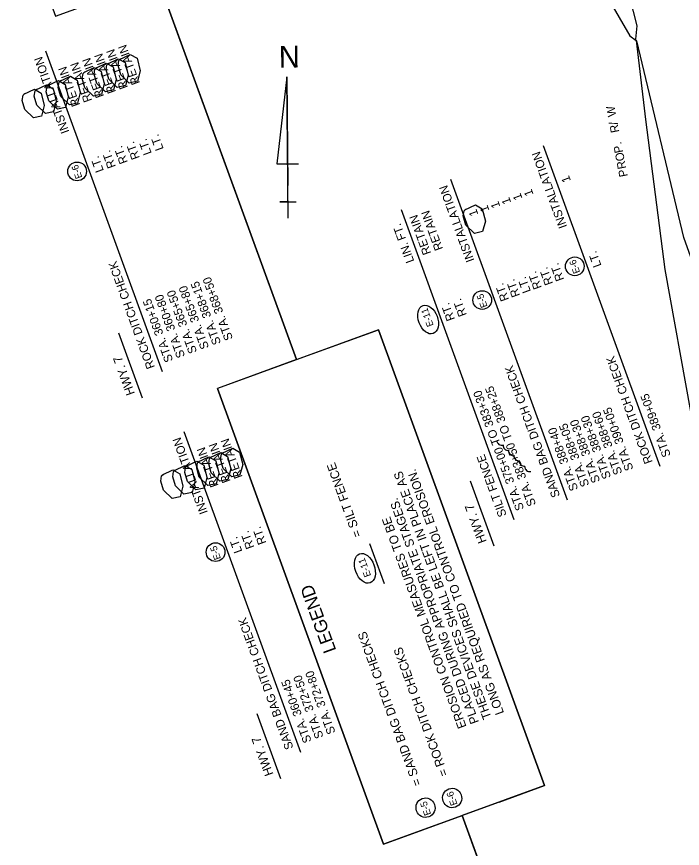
# Model space of a CAD drawing. Extents: x 960650 to 962115, y 1906901 to 1908757.
# Drawn here: x 961228 to 961698, y 1907282 to 1907870 of the extents above; entities that cross this region are included whole.
import ezdxf

# ---------------------------------------------------------------- set-up
doc = ezdxf.new("R2010")
doc.units = 0
for name, color, linetype in [('1', 7, 'Continuous'), ('44', 7, 'Continuous'), ('63', 7, 'Continuous'), ('Level 1', 7, 'Continuous'), ('Level 44', 7, 'Continuous'), ('NO PLOT', 7, 'Continuous'), ('R_Draft', 7, 'Continuous'), ('S_TREE', 7, 'Continuous')]:
    doc.layers.add(name, color=color, linetype=linetype)

msp = doc.modelspace()

# ---------------------------------------------------------------- linework, layer by layer
at = {"layer": '1'}
for p, q in [((961425.36, 1907627.47), (961327.48, 1907896.39)), ((961483.4, 1907648.6), (961369.64, 1907607.19)), ((961486.84, 1907285.2), (961369.64, 1907607.19)), ((961568.72, 1907315), (961486.84, 1907285.2)), ((961624.82, 1907079.46), (961542.56, 1907305.48))]:
    msp.add_line(p, q, dxfattribs=at)
msp.add_lwpolyline([(961568.72, 1907315), (961600.59, 1907326.6), (961483.4, 1907648.6)], dxfattribs=at)
for centre in [(961270.45, 1907760.38), (961622.07, 1907693.36), (961556.67, 1907669.56), (961368.3, 1907491.54)]:
    msp.add_circle(centre, 6.61, dxfattribs=at)
msp.add_ellipse((961518.44, 1907655.78), major_axis=(-3.6, 9.89), ratio=0.638788, dxfattribs=at)
at = {"layer": '44'}
for p, q in [((961330.68, 1907618.95), (961248.25, 1907845.42)), ((961682.37, 1907551.96), (961599.94, 1907778.43)), ((961616.91, 1907528.13), (961534.48, 1907754.6)), ((961579.17, 1907514.4), (961499.55, 1907733.16)), ((961316.61, 1907600.33), (961299.91, 1907646.22)), ((961428.53, 1907350.11), (961346.1, 1907576.58)), ((961565.1, 1907495.78), (961548.39, 1907541.67)), ((961414.46, 1907331.49), (961397.76, 1907377.38))]:
    msp.add_line(p, q, dxfattribs=at)
at = {"layer": '63'}
for p, q in [((961418.69, 1907827.3), (961411.58, 1907765.69)), ((961419.63, 1907727.31), (961418.69, 1907827.3)), ((961418.69, 1907827.3), (961419.41, 1907750.38)), ((961411.58, 1907765.69), (961426.96, 1907765.84)), ((961419.63, 1907727.31), (961419.41, 1907750.38)), ((961413.75, 1907738.79), (961425.29, 1907738.9)), ((961419.52, 1907738.84), (961413.75, 1907738.79)), ((961419.63, 1907727.31), (961419.52, 1907738.84))]:
    msp.add_line(p, q, dxfattribs=at)
at = {"layer": 'Level 1'}
for centre, major_axis, ratio in [((961473.76, 1907480.1), (-3.75, 10.3), 0.622952), ((961535.42, 1907317.88), (2.35, -6.47), 0.97521), ((961516.62, 1907311.04), (2.35, -6.47), 0.97521)]:
    msp.add_ellipse(centre, major_axis=major_axis, ratio=ratio, dxfattribs=at)
at = {"layer": 'Level 44'}
msp.add_lwpolyline([(961487.68, 1907469.14), (961477.37, 1907497.45)], dxfattribs=at)
at = {"layer": 'NO PLOT'}
for points in [[(962114.55, 1907257.7), (961568.91, 1908756.85), (961079.18, 1908578.6), (961182.12, 1908295.76), (961245.55, 1908318.85), (961390.91, 1907919.48), (961327.48, 1907896.39), (961425.36, 1907627.47), (961483.4, 1907648.6), (961600.59, 1907326.6), (961542.56, 1907305.48), (961624.82, 1907079.46)], [(962114.55, 1907257.7), (961568.91, 1908756.85), (961079.18, 1908578.6), (961182.12, 1908295.76), (961245.55, 1908318.85), (961390.91, 1907919.48), (961327.48, 1907896.39), (961425.36, 1907627.47), (961483.4, 1907648.6), (961600.59, 1907326.6), (961542.56, 1907305.48), (961624.82, 1907079.46)], [(962114.55, 1907257.7), (961568.91, 1908756.85), (961079.18, 1908578.6), (961182.12, 1908295.76), (961245.55, 1908318.85), (961390.91, 1907919.48), (961327.48, 1907896.39), (961425.36, 1907627.47), (961483.4, 1907648.6), (961600.59, 1907326.6), (961542.56, 1907305.48), (961624.82, 1907079.46)], [(962114.55, 1907257.7), (961568.91, 1908756.85), (961079.18, 1908578.6), (961182.12, 1908295.76), (961245.55, 1908318.85), (961390.91, 1907919.48), (961327.48, 1907896.39), (961425.36, 1907627.47), (961483.4, 1907648.6), (961600.59, 1907326.6), (961542.56, 1907305.48), (961624.82, 1907079.46)], [(961135.09, 1906901.21), (960730.12, 1908013.86), (960776.54, 1908030.76), (960709.57, 1908214.75), (960723.29, 1908219.74), (960649.59, 1908422.25), (961079.18, 1908578.6), (961182.12, 1908295.76), (961109.77, 1908269.43), (961255.13, 1907870.06), (961327.48, 1907896.39), (961425.36, 1907627.47), (961369.64, 1907607.19), (961486.84, 1907285.2), (961542.56, 1907305.48), (961624.82, 1907079.46)], [(961135.09, 1906901.21), (960730.12, 1908013.86), (960776.54, 1908030.76), (960709.57, 1908214.75), (960723.29, 1908219.74), (960649.59, 1908422.25), (961079.18, 1908578.6), (961182.12, 1908295.76), (961109.77, 1908269.43), (961255.13, 1907870.06), (961327.48, 1907896.39), (961425.36, 1907627.47), (961369.64, 1907607.19), (961486.84, 1907285.2), (961542.56, 1907305.48), (961624.82, 1907079.46)], [(961135.09, 1906901.21), (960730.12, 1908013.86), (960776.54, 1908030.76), (960709.57, 1908214.75), (960723.29, 1908219.74), (960649.59, 1908422.25), (961079.18, 1908578.6), (961182.12, 1908295.76), (961109.77, 1908269.43), (961255.13, 1907870.06), (961327.48, 1907896.39), (961425.36, 1907627.47), (961369.64, 1907607.19), (961486.84, 1907285.2), (961542.56, 1907305.48), (961624.82, 1907079.46)], [(961135.09, 1906901.21), (960730.12, 1908013.86), (960776.54, 1908030.76), (960709.57, 1908214.75), (960723.29, 1908219.74), (960649.59, 1908422.25), (961079.18, 1908578.6), (961182.12, 1908295.76), (961109.77, 1908269.43), (961255.13, 1907870.06), (961327.48, 1907896.39), (961425.36, 1907627.47), (961369.64, 1907607.19), (961486.84, 1907285.2), (961542.56, 1907305.48), (961624.82, 1907079.46)]]:
    msp.add_lwpolyline(points, close=True, dxfattribs=at)
msp.add_lwpolyline([(961546.11, 1908053.77), (961660.88, 1907856.14), (961665.4, 1907852.91), (961665.4, 1907852.91), (961672.08, 1907797.08), (961685.77, 1907691.1), (961721.87, 1907490.67), (961833.17, 1907148.06), (961842.49, 1907149.72), (961765.53, 1907456.14), (961778.4, 1907476.17), (961766.21, 1907525.48), (961699.17, 1907713.63), (961665.82, 1907852.62), (961665.4, 1907852.91), (961665.4, 1907852.91), (961665.39, 1907852.96), (961665.26, 1907853.71), (961666.04, 1907863.2), (961658.05, 1907894.81)], dxfattribs=at)
at = {"layer": 'S_TREE'}
for points in [[(961292.04, 1907836.46), (961299.52, 1907839.95), (961304.35, 1907837.21), (961306.49, 1907828.38), (961304.56, 1907821), (961298.86, 1907819.73), (961292.78, 1907825.61), (961290.92, 1907832.06), (961291.53, 1907835.71), (961292.73, 1907836.93)], [(961292.04, 1907836.46), (961299.52, 1907839.95), (961304.35, 1907837.21), (961306.49, 1907828.38), (961304.56, 1907821), (961298.86, 1907819.73), (961292.78, 1907825.61), (961290.92, 1907832.06), (961291.53, 1907835.71), (961292.73, 1907836.93)], [(961300.5, 1907839.54), (961307.97, 1907843.02), (961312.8, 1907840.29), (961314.95, 1907831.46), (961313.02, 1907824.08), (961307.31, 1907822.81), (961301.23, 1907828.69), (961299.38, 1907835.14), (961299.99, 1907838.79), (961301.18, 1907840.01)], [(961300.5, 1907839.54), (961307.97, 1907843.02), (961312.8, 1907840.29), (961314.95, 1907831.46), (961313.02, 1907824.08), (961307.31, 1907822.81), (961301.23, 1907828.69), (961299.38, 1907835.14), (961299.99, 1907838.79), (961301.18, 1907840.01)], [(961275.13, 1907830.3), (961282.6, 1907833.79), (961287.43, 1907831.05), (961289.58, 1907822.23), (961287.65, 1907814.85), (961281.94, 1907813.57), (961275.86, 1907819.46), (961274, 1907825.9), (961274.62, 1907829.56), (961275.81, 1907830.78)], [(961283.59, 1907833.38), (961291.06, 1907836.87), (961295.89, 1907834.13), (961298.04, 1907825.31), (961296.1, 1907817.92), (961290.4, 1907816.65), (961284.32, 1907822.54), (961282.46, 1907828.98), (961283.07, 1907832.64), (961284.27, 1907833.86)], [(961258.21, 1907824.15), (961265.69, 1907827.63), (961270.52, 1907824.9), (961272.67, 1907816.07), (961270.73, 1907808.69), (961265.03, 1907807.42), (961258.95, 1907813.3), (961257.09, 1907819.75), (961257.7, 1907823.4), (961258.9, 1907824.62)], [(961258.21, 1907824.15), (961265.69, 1907827.63), (961270.52, 1907824.9), (961272.67, 1907816.07), (961270.73, 1907808.69), (961265.03, 1907807.42), (961258.95, 1907813.3), (961257.09, 1907819.75), (961257.7, 1907823.4), (961258.9, 1907824.62)], [(961241.3, 1907817.99), (961248.77, 1907821.48), (961253.6, 1907818.74), (961255.75, 1907809.91), (961253.82, 1907802.53), (961248.11, 1907801.26), (961242.03, 1907807.14), (961240.18, 1907813.59), (961240.79, 1907817.24), (961241.98, 1907818.47)], [(961241.3, 1907817.99), (961248.77, 1907821.48), (961253.6, 1907818.74), (961255.75, 1907809.91), (961253.82, 1907802.53), (961248.11, 1907801.26), (961242.03, 1907807.14), (961240.18, 1907813.59), (961240.79, 1907817.24), (961241.98, 1907818.47)], [(961241.3, 1907817.99), (961248.77, 1907821.48), (961253.6, 1907818.74), (961255.75, 1907809.91), (961253.82, 1907802.53), (961248.11, 1907801.26), (961242.03, 1907807.14), (961240.18, 1907813.59), (961240.79, 1907817.24), (961241.98, 1907818.47)], [(961249.76, 1907821.07), (961257.23, 1907824.55), (961262.06, 1907821.82), (961264.21, 1907812.99), (961262.27, 1907805.61), (961256.57, 1907804.34), (961250.49, 1907810.22), (961248.63, 1907816.67), (961249.25, 1907820.32), (961250.44, 1907821.54)], [(961249.76, 1907821.07), (961257.23, 1907824.55), (961262.06, 1907821.82), (961264.21, 1907812.99), (961262.27, 1907805.61), (961256.57, 1907804.34), (961250.49, 1907810.22), (961248.63, 1907816.67), (961249.25, 1907820.32), (961250.44, 1907821.54)], [(961249.76, 1907821.07), (961257.23, 1907824.55), (961262.06, 1907821.82), (961264.21, 1907812.99), (961262.27, 1907805.61), (961256.57, 1907804.34), (961250.49, 1907810.22), (961248.63, 1907816.67), (961249.25, 1907820.32), (961250.44, 1907821.54)], [(961232.84, 1907814.91), (961240.32, 1907818.4), (961245.14, 1907815.66), (961247.29, 1907806.84), (961245.36, 1907799.45), (961239.65, 1907798.18), (961233.58, 1907804.07), (961231.72, 1907810.51), (961232.33, 1907814.17), (961233.52, 1907815.39)], [(961232.84, 1907814.91), (961240.32, 1907818.4), (961245.14, 1907815.66), (961247.29, 1907806.84), (961245.36, 1907799.45), (961239.65, 1907798.18), (961233.58, 1907804.07), (961231.72, 1907810.51), (961232.33, 1907814.17), (961233.52, 1907815.39)], [(961544.44, 1907733.33), (961551.91, 1907736.82), (961556.74, 1907734.08), (961558.89, 1907725.25), (961556.95, 1907717.87), (961551.25, 1907716.6), (961545.17, 1907722.48), (961543.31, 1907728.93), (961543.92, 1907732.58), (961545.12, 1907733.81)], [(961372.98, 1907561.46), (961380.45, 1907564.95), (961385.28, 1907562.21), (961387.43, 1907553.39), (961385.49, 1907546.01), (961379.79, 1907544.73), (961373.71, 1907550.62), (961371.85, 1907557.06), (961372.47, 1907560.72), (961373.66, 1907561.94)], [(961372.98, 1907561.46), (961380.45, 1907564.95), (961385.28, 1907562.21), (961387.43, 1907553.39), (961385.49, 1907546.01), (961379.79, 1907544.73), (961373.71, 1907550.62), (961371.85, 1907557.06), (961372.47, 1907560.72), (961373.66, 1907561.94)], [(961356.06, 1907555.31), (961363.54, 1907558.79), (961368.37, 1907556.06), (961370.52, 1907547.23), (961368.58, 1907539.85), (961362.88, 1907538.58), (961356.8, 1907544.46), (961354.94, 1907550.91), (961355.55, 1907554.56), (961356.75, 1907555.78)], [(961364.52, 1907558.38), (961371.99, 1907561.87), (961376.82, 1907559.14), (961378.97, 1907550.31), (961377.04, 1907542.93), (961371.33, 1907541.65), (961365.25, 1907547.54), (961363.4, 1907553.98), (961364.01, 1907557.64), (961365.2, 1907558.86)], [(961364.52, 1907558.38), (961371.99, 1907561.87), (961376.82, 1907559.14), (961378.97, 1907550.31), (961377.04, 1907542.93), (961371.33, 1907541.65), (961365.25, 1907547.54), (961363.4, 1907553.98), (961364.01, 1907557.64), (961365.2, 1907558.86)], [(961364.52, 1907558.38), (961371.99, 1907561.87), (961376.82, 1907559.14), (961378.97, 1907550.31), (961377.04, 1907542.93), (961371.33, 1907541.65), (961365.25, 1907547.54), (961363.4, 1907553.98), (961364.01, 1907557.64), (961365.2, 1907558.86)], [(961339.15, 1907549.15), (961346.62, 1907552.64), (961351.45, 1907549.9), (961353.6, 1907541.07), (961351.67, 1907533.69), (961345.96, 1907532.42), (961339.88, 1907538.3), (961338.03, 1907544.75), (961338.64, 1907548.4), (961339.83, 1907549.63)], [(961339.15, 1907549.15), (961346.62, 1907552.64), (961351.45, 1907549.9), (961353.6, 1907541.07), (961351.67, 1907533.69), (961345.96, 1907532.42), (961339.88, 1907538.3), (961338.03, 1907544.75), (961338.64, 1907548.4), (961339.83, 1907549.63)], [(961347.61, 1907552.23), (961355.08, 1907555.71), (961359.91, 1907552.98), (961362.06, 1907544.15), (961360.12, 1907536.77), (961354.42, 1907535.5), (961348.34, 1907541.38), (961346.48, 1907547.83), (961347.09, 1907551.48), (961348.29, 1907552.7)], [(961347.61, 1907552.23), (961355.08, 1907555.71), (961359.91, 1907552.98), (961362.06, 1907544.15), (961360.12, 1907536.77), (961354.42, 1907535.5), (961348.34, 1907541.38), (961346.48, 1907547.83), (961347.09, 1907551.48), (961348.29, 1907552.7)], [(961330.69, 1907546.07), (961338.16, 1907549.56), (961342.99, 1907546.82), (961345.14, 1907538), (961343.21, 1907530.61), (961337.5, 1907529.34), (961331.43, 1907535.23), (961329.57, 1907541.67), (961330.18, 1907545.33), (961331.37, 1907546.55)], [(961330.69, 1907546.07), (961338.16, 1907549.56), (961342.99, 1907546.82), (961345.14, 1907538), (961343.21, 1907530.61), (961337.5, 1907529.34), (961331.43, 1907535.23), (961329.57, 1907541.67), (961330.18, 1907545.33), (961331.37, 1907546.55)]]:
    msp.add_lwpolyline(points, dxfattribs=at)
for centre, start, end in [((961570.54, 1907570.63), 184.76269, 286.3596), ((961575.11, 1907566.93), 174.70328, 276.30019), ((961578.91, 1907563.23), 174.70328, 276.30019), ((961582.73, 1907559.58), 174.65509, 276.252), ((961586.48, 1907555.79), 174.65509, 276.252), ((961590.36, 1907551.99), 179.44033, 281.03724)]:
    msp.add_arc(centre, 3.64, start, end, dxfattribs=at)

# ---------------------------------------------------------------- texts
at = {"layer": '1'}
for s, rotation, p in [('E-6 ', 110, (961274.19, 1907756.2)), ('E-6 ', 110, (961625.87, 1907689.21)), ('E-5 ', 110, (961560.52, 1907665.1)), ('E-11', 109.99998, (961522.43, 1907651.7)), ('E-5 ', 110, (961372.14, 1907487.08))]:
    msp.add_text(s, height=4.8, rotation=rotation, dxfattribs=at).set_placement(p)
at = {"layer": '44'}
for s, height, rotation, p in [('RETAIN', 6, 110, (961306.49, 1907819.73)), ('RETAIN', 6, 110, (961314.94, 1907822.81)), ('INSTALLATION', 6, 110, (961265.03, 1907788.36)), ('RETAIN', 6, 110, (961289.57, 1907813.58)), ('RETAIN', 6, 110, (961298.03, 1907816.66)), ('RETAIN', 6, 110, (961272.66, 1907807.42)), ('RETAIN', 6, 110, (961281.11, 1907810.5)), ('LT.', 6, 110, (961331.7, 1907776.29)), ('RT.', 6, 110, (961314.83, 1907770)), ('LT.', 6, 110, (961323.24, 1907773.21)), ('RT.', 6, 110, (961297.92, 1907763.84)), ('RT.', 6, 110, (961306.38, 1907766.92)), ('LT.', 6, 110, (961289.41, 1907760.9)), ('INSTALLATION', 6, 110, (961616.71, 1907721.37)), ('1', 6, 110, (961619.39, 1907753.79)), ('INSTALLATION', 6, 110, (961551.25, 1907697.54)), ('1', 6, 110, (961585.17, 1907741.33)), ('1', 6, 110, (961593, 1907744.18)), ('1', 6, 110, (961569.51, 1907735.63)), ('1', 6, 110, (961577.19, 1907738.43)), ('1', 6, 110, (961554.01, 1907729.99)), ('1', 6, 110, (961561.84, 1907732.84)), ('RETAIN', 6, 109.99998, (961520.67, 1907702.7)), ('RETAIN', 6, 109.99998, (961529.07, 1907705.76)), ('LIN. FT.', 6, 109.99998, (961508.73, 1907696.97)), ('LT.', 6, 110, (961641.02, 1907693.88)), ('ROCK DITCH CHECK', 6, 110, (961325.52, 1907622.17)), ('RT.', 6, 110, (961606.85, 1907681.29)), ('RT.', 6, 110, (961614.68, 1907684.14)), ('RT.', 6, 110, (961598.87, 1907678.38)), ('STA. 368+15', 6, 110, (961372.19, 1907639.15)), ('STA. 368+50', 6, 110, (961380.65, 1907642.23)), ('RT.', 6, 110, (961575.69, 1907669.95)), ('RT.', 6, 110, (961583.51, 1907672.8)), ('LT.', 6, 110, (961591.14, 1907675.72)), ('STA. 365+50', 6, 110, (961355.28, 1907633)), ('STA. 365+80', 6, 110, (961363.73, 1907636.08)), ('STA. 360+15', 6, 110, (961338.36, 1907626.84)), ('STA. 360+80', 6, 110, (961346.82, 1907629.92)), ('RT.', 6, 109.99998, (961545.88, 1907659.1)), ('RT.', 6, 109.99998, (961537.47, 1907656.04)), ('HWY. 7', 6.25, 110, (961311.4, 1907603.59)), ('ROCK DITCH CHECK', 6, 110, (961677.2, 1907555.18)), ('SAND BAG DITCH CHECK', 6, 110, (961611.74, 1907531.35)), ('STA. 375+00 TO 383+30', 6, 109.99998, (961586.37, 1907522.12)), ('STA. 383+50 TO 388+25', 6, 109.99998, (961594.78, 1907525.18)), ('STA. 389+05', 6, 110, (961689.97, 1907559.82)), ('STA. 390+05', 6, 110, (961663.58, 1907550.22)), ('STA. 388+30', 6, 110, (961647.77, 1907544.46)), ('STA. 388+60', 6, 110, (961655.75, 1907547.37)), ('STA. 388+05', 6, 110, (961632.41, 1907538.88)), ('STA. 388+30', 6, 110, (961640.09, 1907541.67)), ('STA. 388+40', 6, 110, (961624.58, 1907536.03)), ('INSTALLATION', 6, 110, (961362.88, 1907519.52)), ('RETAIN', 6, 110, (961387.42, 1907544.74)), ('RETAIN', 6, 110, (961370.51, 1907538.58)), ('RETAIN', 6, 110, (961378.96, 1907541.66)), ('SILT FENCE      ', 6, 109.99998, (961574, 1907517.62)), ('HWY. 7', 6.25, 110, (961559.89, 1907499.03)), ('RT.', 6, 110, (961395.77, 1907495)), ('RT.', 6, 110, (961404.23, 1907498.08)), ('LT.', 6, 110, (961387.26, 1907492.06)), ('SAND BAG DITCH CHECK', 6, 110, (961423.37, 1907353.33)), ('STA. 372+50', 6, 110, (961444.67, 1907361.08)), ('STA. 372+80', 6, 110, (961453.13, 1907364.16)), ('STA. 360+45', 6, 110, (961436.21, 1907358)), ('HWY. 7', 6.25, 110, (961409.25, 1907334.75))]:
    msp.add_text(s, height=height, rotation=rotation, dxfattribs=at).set_placement(p)
at = {"layer": '63'}
msp.add_text('N', height=15.38, rotation=0.53522, dxfattribs=at).set_placement((961413, 1907833.66))
at = {"layer": 'Level 1'}
for s, height, p in [('= SILT FENCE', 6.25, (961471.51, 1907503.16)), ('THESE DEVICES SHALL BE LEFT IN PLACE AS ', 6.25, (961563.34, 1907374.73)), ('LONG AS REQUIRED TO CONTROL EROSION.', 6.25, (961572.18, 1907377.95)), ('PLACED DURING APPROPRIATE STAGES. ', 6.25, (961554.5, 1907371.51)), ('EROSION CONTROL MEASURES TO BE', 6.25, (961545.65, 1907368.29)), ('E-11 ', 4.876, (961478.2, 1907474.92)), ('= SAND BAG DITCH CHECKS', 6.25, (961513.91, 1907327.64)), ('= ROCK DITCH CHECKS', 6.25, (961532.7, 1907334.48)), ('E-6 ', 4.876, (961539.27, 1907313.52)), ('E-5 ', 4.876, (961520.64, 1907306.5))]:
    msp.add_text(s, height=height, rotation=110.00001, dxfattribs=at).set_placement(p)
at = {"layer": 'Level 44'}
msp.add_text('LEGEND', height=9.143, rotation=110.00001, dxfattribs=at).set_placement((961453.67, 1907422.25))
at = {"layer": 'R_Draft'}
for s, p in [('W', (961651.41, 1907799.59)), ('/', (961652.51, 1907793.83)), ('R', (961653.58, 1907788.27)), ('.', (961655.26, 1907779.5)), ('P', (961656.33, 1907773.93)), ('O', (961657.43, 1907768.17)), ('R', (961658.5, 1907762.61)), ('P', (961659.57, 1907757.04))]:
    msp.add_text(s, height=6, rotation=100.8503, dxfattribs=at).set_placement(p)

doc.saveas('drawing.dxf')
